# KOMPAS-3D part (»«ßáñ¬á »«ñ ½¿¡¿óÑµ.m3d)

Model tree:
1. Эскиз:1
2. Операция выдавливания:1
     Расстояние 1 = 1
3. Эскиз:2
4. Вырезать элемент выдавливания:1
     Расстояние 1 = 0.5; Угол 1 = 8
5. Массив по концентрической сетке:1  (with: Вырезать элемент выдавливания:1)  (labels: Экземпляр ( 1, 1 ); Экземпляр ( 1, 2 ); Экземпляр ( 1, 3 ); Экземпляр ( 1, 4 ))
     N 2 = 8; Шаг 2 = 360; Номер 2 = 1
6. Эскиз:3
7. Отверстие:1
8. Эскиз:4
9. Операция выдавливания:2
     Расстояние 1 = 2

Referenced files in C:\Program Files\ASCON\KOMPAS-3D V13 Home\Sys\: holelib.lfr
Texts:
  посадка под линивец
  Сплав АЛ8  ГОСТ 1583-93
  Отверстие 01
  (вариант 1)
